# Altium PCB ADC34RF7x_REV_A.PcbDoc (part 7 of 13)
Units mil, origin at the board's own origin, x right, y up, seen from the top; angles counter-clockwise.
Board outline 6250 x 2716.54 mil, 18 copper layers (Top Layer, L2 GND, L3 PWR, L4 GND, L5 PWR/SIG, L6 GND, L7 SIGNAL, L8 GND, L9 GND, L10 SIGNAL, L11 GND, L12 SIGNAL, L13 GND, L14 PWR, L15 GND, L16 PWR/SIG, L16 GND, Bottom Layer), stack 95.314 mil thick; 668 components, 786 nets, 3150 pads, 2020 vias.
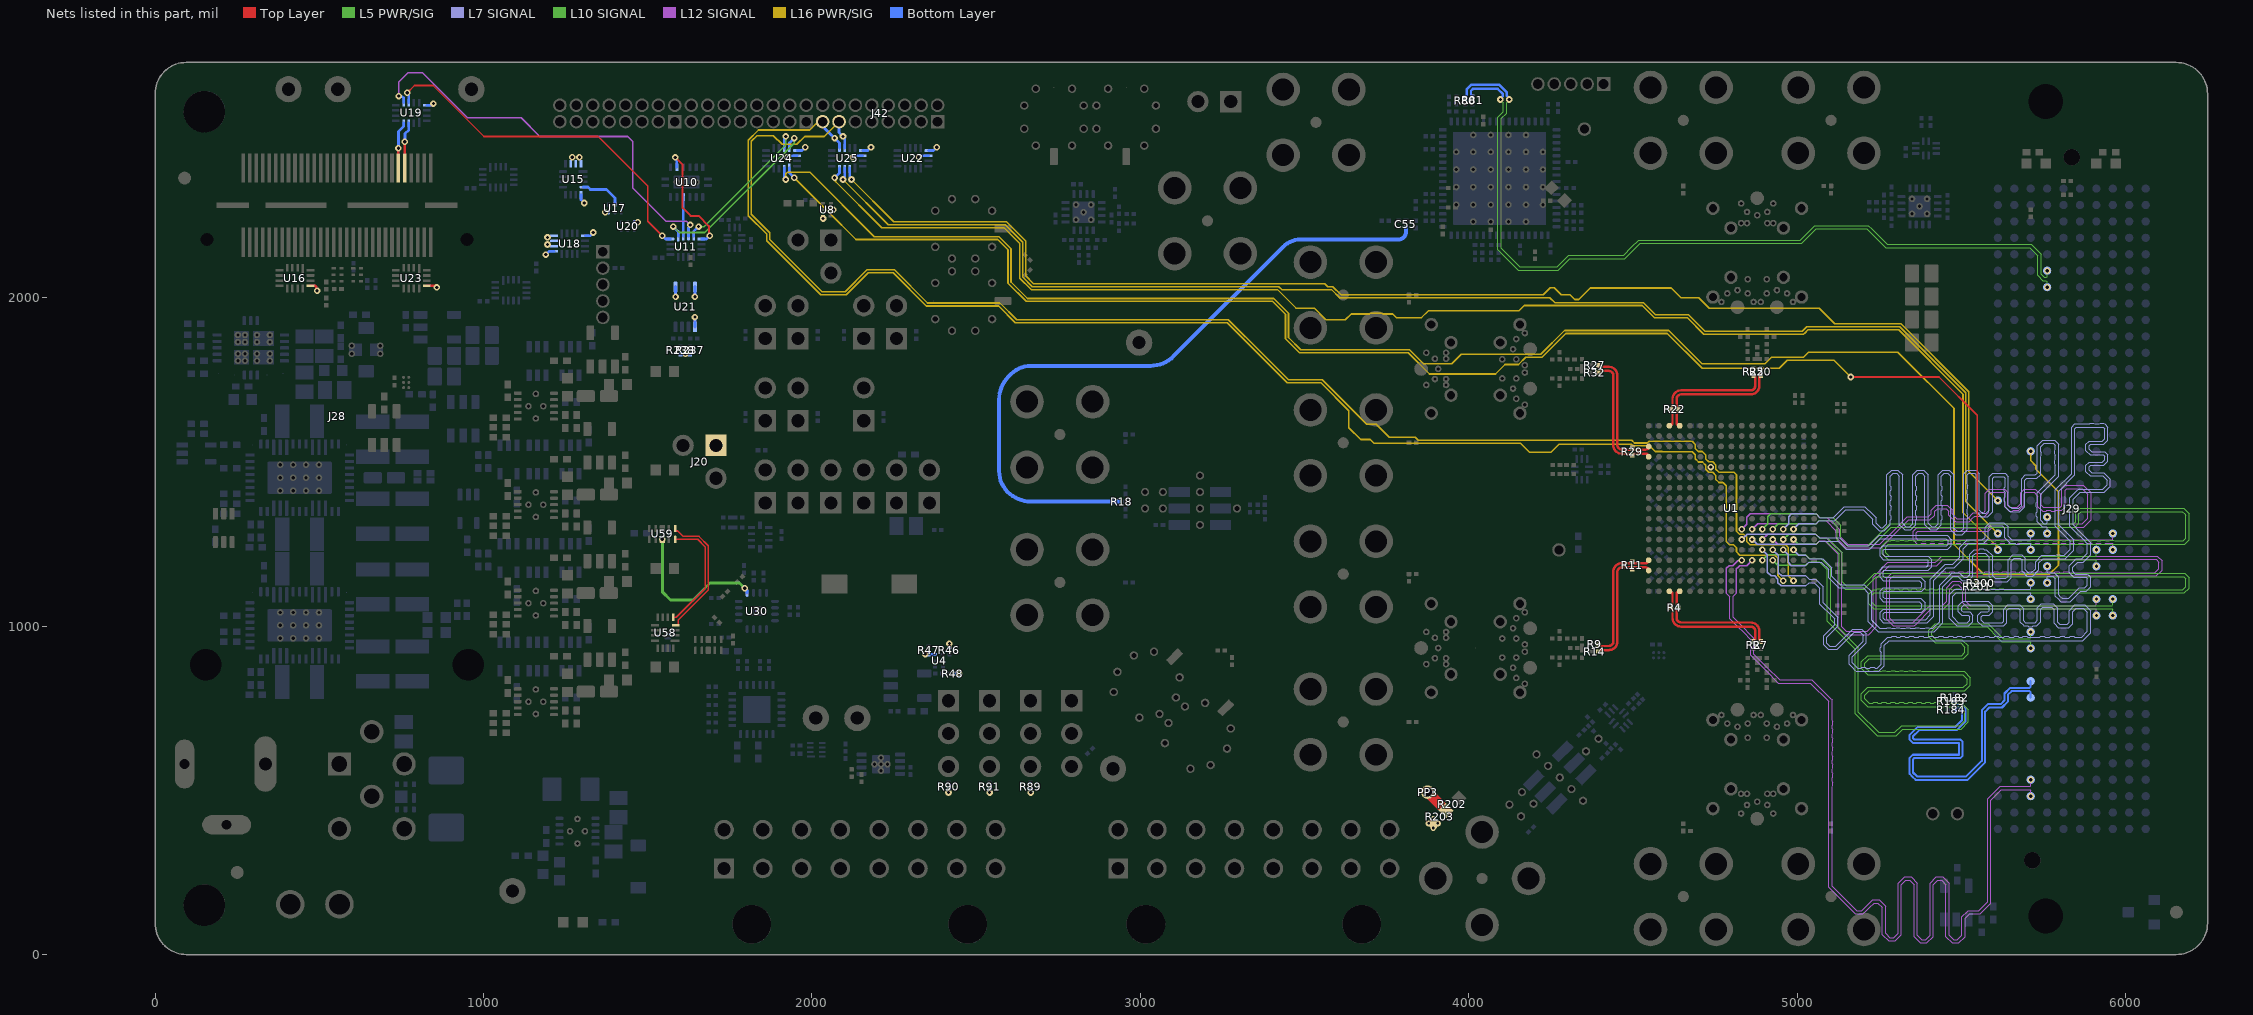
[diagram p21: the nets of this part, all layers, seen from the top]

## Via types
v1: diameter 20, hole 10, Top Layer to Bottom Layer, tented both sides, 1793 vias
v2: diameter 24, hole 12, Top Layer to Bottom Layer, tented both sides, 168 vias
v3: diameter 18, hole 8, Top Layer to Bottom Layer, tented both sides, 59 vias

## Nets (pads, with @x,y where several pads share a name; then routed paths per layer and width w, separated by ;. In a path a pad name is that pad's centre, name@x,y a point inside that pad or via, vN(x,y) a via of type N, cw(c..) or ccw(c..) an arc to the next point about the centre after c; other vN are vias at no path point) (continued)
GPIO21_FPGA: J29.K20 U25.2 | length 4184
  L16 PWR/SIG w5: v1(2120.5,2360.04) 2249.44,2231.1 2592.63,2231.1 2651.15,2172.58 2651.15,2066.73 2675.07,2042.81 3561.6,2042.81 3570.6,2033.81 3586.14,2033.81 3610.95,2009 4226.78,2009 4247.92,2030.15 4260.77,2030.15 4281.92,2009 4308.22,2009 4322.56,1994.66 4335.4,1994.66 4370.4,2029.66 4616.6,2029.66 4646.26,2000 4700.45,2000 4732.45,1968 5067.27,1968 5114.94,1920.33 5316.57,1920.33 5523,1713.9 5523,1470.69 v1(5611.42,1382.27)
  Bottom Layer w8: U25.2@2115.5,2395.04 U25.2@2115.5,2393.07 2115.5,2368.28 2120.5,2363.28 v1(2120.5,2360.04)
GPIO22_ADC: J42.13 U1.C16 U25.10 | length 4520.3
  L16 PWR/SIG w5: J42.13@2082.62,2536.06 2037.62,2491.06 1978.09,2491.06 1954.1,2467.07 1909.24,2467.07 1882.62,2493.69 1832.79,2493.69 1815.27,2476.17 1815.27,2253.78 1871.39,2197.67 1871.39,2177.04 2030.57,2017.86 2101.18,2017.86 2168.05,2084.73 2251.48,2084.73 2352.21,1984 2572.56,1984 2623.36,1933.2 3268.22,1933.2 3374.43,1827 3451.32,1750.11 3553.84,1750.11 3689.65,1614.3 3718.8,1614.3 3758.3,1574.81 3837.19,1574.81 3846.19,1565.81 4496.61,1565.81 4504.64,1557.78 4544.11,1557.78 4549.56,1563.24 4589.03,1563.24 4589.53,1562.74 4680.44,1562.74 4689.84,1553.34 4689.84,1540.99 4699.25,1531.59 4711.59,1531.59 4721.32,1521.86 4721.32,1509.51 4730.71,1500.12 4743.06,1500.12 4752.76,1490.42 4752.76,1478.08 4762.08,1468.75 4807.62,1468.75 4815.5,1460.87 4815.5,1288.9 4825.12,1279.28 4837.92,1279.28 4847,1270.2 4847,1257.4 4856.62,1247.78 4965.21,1247.78 4973.48,1239.52 4973.48,1153.3 v1(4988.98,1137.8)
  Bottom Layer w8: J42.13@2082.62,2536.06 2082.62,2503.19 v1(2094.75,2491.06) 2094.75,2487.81 v1@2099.75,2482.81 ; U25.10@2099.75,2456.06 v1@2099.75,2482.81 ; v1@2099.75,2491.06 v1@2099.75,2482.81
GPIO22_FPGA: J29.K22 U25.3 | length 4266.9
  L16 PWR/SIG w5: v1(2094.75,2360.04) 2232.69,2222.1 2588.91,2222.1 2642.15,2168.85 2642.15,2063 2671.34,2033.81 3421.47,2033.81 3430.47,2024.81 3582.41,2024.81 3607.22,2000 4247.07,2000 4261.84,1985.23 4531.98,1985.23 4569.59,1947.63 4669.8,1947.63 4719.56,1897.87 5015.76,1897.87 5029.22,1911.33 5312.85,1911.33 5514,1710.17 5514,1379.69 v1(5611.42,1282.27)
  Bottom Layer w8: v1(2094.75,2360.04) 2094.75,2363.28 2099.75,2368.28 U25.3@2099.75,2393.07 U25.3@2099.75,2395.04
GPIO23_ADC: J42.15 U1.D16 U25.9 | length 4491.8
  L16 PWR/SIG w5: J42.15@2032.62,2536.06 2025.67,2529.11 2011.4,2529.11 1993.09,2510.8 1837.17,2510.8 1806.27,2479.9 1806.27,2250.06 1862.39,2193.94 1862.39,2173.31 2026.84,2008.86 2104.91,2008.86 2171.78,2075.73 2247.75,2075.73 2348.48,1975 2568.83,1975 2619.63,1924.2 3264.49,1924.2 3368.06,1820.63 3447.59,1741.11 3550.12,1741.11 3635,1656.22 3635,1604.26 3670.84,1568.42 3699.86,1568.42 3711.47,1556.81 4157.97,1556.81 4184.99,1529.79 4250.74,1529.79 4275.29,1554.34 4495.36,1554.34 4500.91,1548.78 4550.68,1548.78 4567.72,1531.74 4589.03,1531.74 4589.53,1531.25 4680.44,1531.25 4690,1521.69 4690,1509.34 4699.56,1499.78 4711.9,1499.78 4721.45,1490.24 4721.45,1477.89 4730.96,1468.38 4743.3,1468.38 4752.76,1458.93 4752.76,1446.58 4762.08,1437.26 4773.63,1437.26 4774.13,1436.76 4774.92,1436.76 4784.01,1427.67 4784.01,1257.85 4794.08,1247.78 4806.42,1247.78 4815.5,1238.7 4815.5,1226.36 4825.59,1216.26 4932.4,1216.26 4941.98,1206.69 4941.98,1153.3 v1(4957.48,1137.8)
  Bottom Layer w8: J42.15@2032.62,2536.06 2039,2529.68 2039,2516.06 2084,2471.06 ; v1(2069,2486.06) 2084,2471.06 ; U25.9@2084,2456.06 2084,2471.06
GPIO23_FPGA: J29.K23 U25.4 | length 4387.9
  L16 PWR/SIG w5: v1(2069,2365.04) 2071.87,2362.17 2071.87,2353.75 2212.52,2213.1 2585.18,2213.1 2633.15,2165.12 2633.15,2059.27 2667.62,2024.81 3417.74,2024.81 3474.1,1968.44 3529.31,1968.44 3564.55,1933.2 3611.21,1933.2 3611.64,1932.77 3624.48,1932.77 3642.05,1950.34 3697.96,1950.34 3699.85,1952.23 3736.27,1952.23 3738.16,1950.34 3768.81,1950.34 3779.6,1939.55 3856.44,1939.55 3877.62,1960.73 4153.42,1960.73 4168.92,1976.23 4528.26,1976.23 4565.86,1938.63 4666.08,1938.63 4715.83,1888.87 5019.49,1888.87 5022.89,1892.27 5032.95,1902.33 5309.12,1902.33 5505,1706.45 5505,1345.93 5608.55,1242.38 5608.55,1235.14 v1(5611.42,1232.27)
  Bottom Layer w8: v1(2069,2365.04) 2084,2380.04 U25.4@2084,2393.07 U25.4@2084,2395.04
GPIO_MUX0_FT: J28.9 U19.3 | length 143.1
  Top Layer w8: J28.9@760.27,2395 v1(760.27,2475)
  Bottom Layer w8: v1(760.27,2475) 761.1,2475.84 761.1,2499.69 772.4,2510.98 U19.3@772.4,2533.03
GPIO_MUX1_FT: J28.11 U19.4 | length 144.6
  Top Layer w8: J28.11@740.91,2395 v1(740.91,2455)
  Bottom Layer w8: v1(740.91,2455) 740.99,2455.08 740.99,2506.07 756.65,2521.73 U19.4@756.65,2533.03
GPIO_MUX_0: U10.13 U11.2 | length 120
  Bottom Layer w8: U11.2@1608.5,2186.65 U10.13@1608.5,2306.65
GPIO_MUX_0_FMC_GPIOVDD: U11.1 U24.12 | length 576.4
  L5 PWR/SIG w5: v1(1577.76,2216.65) 1595.79,2198.62 1674.13,2198.62 1946.25,2470.74 v1(1946.25,2486.06)
  Bottom Layer w8: v1(1577.76,2216.65) 1592.76,2201.65 U11.1@1592.76,2186.65 ; U24.12@1931.25,2456.06 1931.25,2471.06 v1(1946.25,2486.06)
GPIO_MUX_0_FPGA: R200.1 R201.2 U24.1 | length 4674.4
  Top Layer w5: v1(5163.54,1758.63) 5432.03,1758.63 5548.71,1641.96 R200.1@5548.71,1131.13
  L16 PWR/SIG w5: v1(1946.25,2365.04) 2049.54,2261.74 2049.54,2261.63 2134.07,2177.1 2565.75,2177.1 2597.15,2145.7 2597.15,2044.36 2652.7,1988.81 3402.83,1988.81 3442.19,1949.44 3442.19,1875.17 3484.82,1832.55 3815.96,1832.55 3880.74,1767.77 3900.69,1767.77 3913.53,1767.77 4081.5,1767.77 4110.5,1796.77 4151.53,1796.77 4173.53,1818.77 4223.19,1818.77 4295.69,1891.27 4605.06,1891.27 4710.83,1785.5 4945.42,1785.5 4969.79,1809.87 5112.31,1809.87 v1(5163.54,1758.63)
  Bottom Layer w8: U24.1@1931.25,2395.04 1931.25,2380.04 v1(1946.25,2365.04)
GPIO_MUX_0_USB_GPIOVDD: U11.16 U19.10 | length 1099.8
  Top Layer w5: v1(767.4,2624.06) 789.58,2646.23 846.23,2646.23 1001.4,2491.06 1348.94,2491.06 1500,2340 1500,2232.91 v1(1544.13,2188.78)
  Bottom Layer w8: v1(767.4,2624.06) 767.4,2620.81 772.4,2615.81 U19.10@772.4,2594.06 ; v1(1544.13,2188.78) 1544.92,2188.78 1547.22,2186.48 1547.22,2185.69 1554.13,2178.78 U11.16@1569.13,2178.78
GPIO_MUX_1: U10.3 U11.5 | length 357.7
  Top Layer w6: v1(1583.82,2427.2) 1606.24,2404.78 1606.24,2273.71 1630.62,2249.33 1654.83,2249.33 1685.98,2218.18 1685.98,2191.42 v1(1688.62,2188.78)
  Bottom Layer w8: v1(1583.82,2427.2) 1583.82,2423.96 1588.82,2418.96 U10.3@1588.82,2397.2 ; U11.5@1663.62,2178.78 1678.62,2178.78 1685.54,2185.69 1685.54,2186.48 1687.83,2188.78 v1(1688.62,2188.78)
GPIO_MUX_1_FMC_GPIOVDD: U11.4 U24.11 | length 467.6
  L5 PWR/SIG w5: v1(1655,2216.65) 1671.89,2216.65 1920.5,2465.26 v1(1920.5,2491.06)
  Bottom Layer w8: U11.4@1640,2186.65 1640,2201.65 v1(1655,2216.65) ; U24.11@1915.5,2456.06 1915.5,2482.81 1920.5,2487.81 v1(1920.5,2491.06)
GPIO_MUX_1_FPGA: J29.H17 U24.2 | length 5290.3
  L16 PWR/SIG w5: v1(1920.5,2360.04) 1920.5,2377.46 1924.57,2381.54 1994.57,2381.54 2190.02,2186.1 2569.48,2186.1 2606.15,2149.42 2606.15,2048.09 2656.43,1997.81 3406.55,1997.81 3451.19,1953.17 3451.19,1878.9 3488.55,1841.55 3819.69,1841.55 3850.63,1810.61 3862.47,1798.77 3948.04,1798.77 3977.04,1827.77 4219.46,1827.77 4291.96,1900.27 4608.79,1900.27 4709.63,1799.43 4902.87,1799.43 4922.31,1818.87 5019.6,1818.87 5035,1834.27 5306.77,1834.27 5322.17,1818.87 5478,1663.04 5478,1248.27 5568.27,1158 5768.27,1158 5795.92,1185.65 5795.92,1409.35 5726.92,1478.35 5726.92,1488.69 5711.42,1504.19 v1(5711.42,1532.27)
  Bottom Layer w8: U24.2@1915.5,2395.04 U24.2@1915.5,2393.07 1915.5,2368.28 1920.5,2363.28 v1(1920.5,2360.04)
GPIO_MUX_1_USB_GPIOVDD: U11.3 U19.9 | length 1285.5
  L12 SIGNAL w5: v1(741.65,2614.06) 741.65,2656.65 770,2685 814.11,2685 951.43,2547.68 1114.81,2547.68 1171.43,2491.06 1438.94,2491.06 1455,2475 1455,2333.24 1555.65,2232.59 1618.31,2232.59 v1(1629.25,2221.65)
  Bottom Layer w8: v1(741.65,2614.06) 743.95,2611.76 753.1,2611.76 756.65,2608.2 U19.9@756.65,2594.06 ; U11.3@1624.25,2186.65 1624.25,2213.41 1629.25,2218.41 v1(1629.25,2221.65)
GPIOVADJ: PP3.1 R89.2 R90.2 R91.2 R202.2 R203.1 R237.2 R238.2 U15.5 U15.14 U15.15 U15.16 U16.13 U17.6 U18.5 U18.14 U18.15 U18.16 U20.6 U21.1 U21.5 U22.14 U24.14 U25.14 | length 397
  Top Layer w8: U16.13@473.19,2036.26 487.33,2036.26 490.89,2032.7 490.89,2023.56 v1(493.19,2021.26)
  Top Layer w32: PP3.1@3874.91,494.48 R203.1@3931.11,438.29
  Bottom Layer w8: U15.5@1296.98,2313.39 1296.98,2298.39 1303.9,2291.47 1304.68,2291.47 1306.98,2289.17 v1(1306.98,2288.39) ; U18.5@1309.38,2188.62 1324.38,2188.62 1331.3,2195.54 1331.3,2196.32 1333.6,2198.62 v1(1334.38,2198.62) ; R238.2@1599.89,1828.32 v3(1614.89,1828.32) R237.2@1629.18,1828.32 ; v1(1924.87,2427.44) 1928.12,2427.44 1933.12,2432.44 U24.14@1954.87,2432.44 ; v1(2124.87,2427.44) 2128.12,2427.44 2133.12,2432.44 U25.14@2154.87,2432.44 ; v1(2324.87,2427.44) 2328.12,2427.44 2333.12,2432.44 U22.14@2354.87,2432.44 ; v1(2416.05,493.41) R90.2@2416.03,500.5 ; v1(2541.05,493.41) R91.2@2541.03,500.5 ; v1(2666.05,493.41) R89.2@2666.03,500.5
  Bottom Layer w10: v1(1370.63,2260) U17.6@1380.63,2260 ; U20.6@1459.37,2230 v1(1469.37,2230) ; v1(1584.81,2003.16) U21.5@1584.81,2033.16 ; U21.1@1643.87,1911.11 v1(1643.87,1941.11)
  other v1: 1194.89,2162.13 1194.89,2183.62 1270.49,2427.87 1291.98,2427.87
GPIOVDD: J20.1 R46.1 R47.1 R48.1 R203.2 U1.L5 U4.6 U8.2 U8.6 U18.13 U19.13 U21.8 U22.13 U23.13 U24.13 U25.13 | length 268.3
  Top Layer w8: U23.13@827.52,2036.26 852.52,2036.26 cw(c852.52,2031.26) v1(857.52,2031.26) ; v1(2034.12,2241.29) U8.6@2034.13,2248.38 ; U8.2@2057.95,2268.06 v1(2065.04,2268.05)
  Bottom Layer w8: U19.13@827.52,2586.18 842.52,2586.18 ccw(c842.52,2591.18) v1(847.52,2591.18) ; v1(1189.89,2131.38) 1190.68,2131.38 1192.98,2133.68 1192.98,2134.46 1199.89,2141.38 U18.13@1214.89,2141.38 ; U24.13@1954.87,2448.19 1969.87,2448.19 1976.78,2455.1 1976.78,2455.89 1979.08,2458.19 v1(1979.87,2458.19) ; U25.13@2154.87,2448.19 2169.87,2448.19 2176.78,2455.1 2176.78,2455.89 2179.08,2458.19 v1(2179.87,2458.19) ; v1(2345.17,914.8) U4.6@2375.16,914.8 ; U22.13@2354.87,2448.19 2369.87,2448.19 2376.78,2455.1 2376.78,2455.89 2379.08,2458.19 v1(2379.87,2458.19) ; R46.1@2418.79,936.85 v1(2418.79,946.85) ; R48.1@2439.26,855.43 v1(2449.26,855.43)
  Bottom Layer w10: v1(1643.87,2003.16) U21.8@1643.87,2033.16
  other v1: 4737.01,1484.25
  other v3: 3892.13,385.17 3877.99,399.31 3906.28,399.31 3892.13,413.45
I-SENSE-MUX: U30.9 U59.8@1544.55,1264.12 | length 465.7
  L10 SIGNAL w9: v1(1544.55,1264.12) 1544.55,1104.68 1569.43,1079.8 1638.46,1079.8 1689.72,1131.05 1779.29,1131.05 v1(1795.19,1115.15)
  Bottom Layer w9: v1@1794.69,1115.15 v1(1795.19,1115.15) 1802.25,1108.09 U30.9@1802.25,1101.13
I-SENSE-MUX-A0: U58.4 U59.1 | length 412.3
  Top Layer w5: U59.1@1583.92,1296.99 1583.92,1291.17 1585.36,1289.73 1591.18,1289.73 1607.79,1273.12 1656.08,1273.12 1684.39,1244.81 1684.39,1110.11 1593.03,1018.75 1593.03,1004.15 1592.09,1003.21 U58.4@1585.08,1003.21
I-SENSE-MUX-A1: U58.5 U59.10 | length 361.6
  Top Layer w5: U58.5@1577.21,1026.83 1586.97,1026.83 1675.39,1115.25 1675.39,1241.08 1652.35,1264.12 U59.10@1583.92,1264.12
INA_ADC_N: R2.2 R4.2 U1.R17 | length 401.4
  Top Layer w7.4: U1.R17@4611.02,1106.3 cw(c4611.02,1096.75) 4620.57,1096.75 4620.57,1061.12 cw(c4615.75,1061.12) R4.2@4615.75,1056.3 cw(c4615.75,1051.48) 4620.57,1051.48 4620.57,1024.56 ccw(c4646.47,1024.56) 4646.47,998.66 4858.83,998.66 cw(c4858.83,985.16) 4872.33,985.16 4872.33,958.25 cw(c4867.51,958.25) R2.2@4867.51,953.43
INA_ADC_P: R4.1 R7.2 U1.P17 | length 401.4
  Top Layer w7.4: U1.P17@4642.52,1106.3 ccw(c4642.52,1096.75) 4632.97,1096.75 4632.97,1061.12 ccw(c4637.8,1061.12) R4.1@4637.8,1056.3 ccw(c4637.8,1051.48) 4632.97,1051.48 4632.97,1024.56 ccw(c4646.47,1024.56) 4646.47,1011.06 4858.83,1011.06 cw(c4858.83,985.16) 4884.73,985.16 4884.73,958.25 ccw(c4889.56,958.25) R7.2@4889.56,953.43
INB_ADC_N: R9.2 R11.2 U1.U14 | length 401.4
  Top Layer w7.4: R9.2@4395.16,944.3 ccw(c4399.98,944.3) 4399.98,939.48 4426.9,939.48 ccw(c4426.9,952.98) 4440.4,952.98 4440.4,1165.34 cw(c4466.3,1165.34) 4466.3,1191.24 4493.21,1191.24 ccw(c4493.21,1196.06) 4498.03,1196.06 ccw(c4502.86,1196.06) 4502.86,1191.24 4538.48,1191.24 ccw(c4538.48,1200.79) U1.U14@4548.03,1200.79
INB_ADC_P: R11.1 R14.2 U1.U15 | length 401.4
  Top Layer w7.4: R14.2@4395.16,922.25 cw(c4399.98,922.25) 4399.98,927.08 4426.9,927.08 ccw(c4426.9,952.98) 4452.8,952.98 4452.8,1165.34 cw(c4466.3,1165.34) 4466.3,1178.84 4493.21,1178.84 cw(c4493.21,1174.02) R11.1@4498.03,1173.99 cw(c4502.85,1174.02) 4502.85,1178.84 4538.48,1178.84 cw(c4538.48,1169.29) U1.U15@4548.03,1169.29
INC_ADC_N: R20.2 R22.2 U1.P1 | length 401.4
  Top Layer w7.4: U1.P1@4642.52,1610.24 cw(c4642.52,1619.78) 4632.97,1619.78 4632.97,1655.41 cw(c4637.8,1655.41) R22.2@4637.8,1660.24 cw(c4637.8,1665.06) 4632.97,1665.06 4632.97,1691.97 cw(c4646.47,1691.97) 4646.47,1705.47 4858.83,1705.47 ccw(c4858.83,1731.37) 4884.73,1731.37 4884.73,1758.28 cw(c4889.56,1758.28) R20.2@4889.56,1763.11
INC_ADC_P: R22.1 R25.2 U1.R1 | length 401.4
  Top Layer w7.4: U1.R1@4611.02,1610.24 ccw(c4611.02,1619.78) 4620.57,1619.78 4620.57,1655.41 ccw(c4615.75,1655.41) R22.1@4615.75,1660.24 ccw(c4615.75,1665.06) 4620.57,1665.06 4620.57,1691.97 cw(c4646.47,1691.97) 4646.47,1717.87 4858.83,1717.87 ccw(c4858.83,1731.37) 4872.33,1731.37 4872.33,1758.28 ccw(c4867.51,1758.28) R25.2@4867.51,1763.11
IND_ADC_N: R27.2 R29.2 U1.U3 | length 401.4
  Top Layer w7.4: R27.2@4395.16,1794.28 ccw(c4399.98,1794.28) 4399.98,1789.46 4426.9,1789.46 cw(c4426.9,1763.56) 4452.8,1763.56 4452.8,1551.2 ccw(c4466.3,1551.2) 4466.3,1537.7 4493.21,1537.7 ccw(c4493.21,1542.52) R29.2@4498.03,1542.52 ccw(c4502.85,1542.52) 4502.85,1537.7 4538.48,1537.7 ccw(c4538.48,1547.24) U1.U3@4548.03,1547.24
IND_ADC_P: R29.1 R32.2 U1.U4 | length 401.4
  Top Layer w7.4: R32.2@4395.16,1772.23 cw(c4399.98,1772.23) 4399.98,1777.06 4426.9,1777.06 cw(c4426.9,1763.56) 4440.4,1763.56 4440.4,1551.2 ccw(c4466.3,1551.2) 4466.3,1525.3 4493.21,1525.3 cw(c4493.21,1520.47) R29.1@4498.03,1520.47 cw(c4502.86,1520.47) 4502.86,1525.3 4538.48,1525.3 cw(c4538.48,1515.75) U1.U4@4548.03,1515.75
LMK_CLK: C55.1 R18.1 | length 2107.2
  Bottom Layer w12.1: R18.1@2932.95,1379.43 2667,1379.43 cw(c2667,1479.43) 2596.29,1408.71 2596.16,1408.84 cw(c2659.33,1472) 2570,1472 2570,1689.58 cw(c2670,1689.58) 2599.29,1760.29 2606.67,1767.67 cw(c2667,1707.35) 2667,1792.66 3031.06,1792.66 ccw(c3031.06,1892.66) 3101.77,1821.95 3434.82,2155 cw(c3488.43,2101.38) 3488.43,2177.21 3786.13,2177.21 ccw(c3786.13,2199.99) 3808.91,2199.99 C55.1@3808.91,2212.16
LMK_CORECLK_N: J29.G7 R81.2 | length 2482.5
  L10 SIGNAL w3.5: v1(4096.71,2603.54) 4096.71,2601.88 4105.21,2593.38 4105.21,2566.19 4089.08,2550.06 4089.08,2146.29 4151.14,2084.23 4273.23,2084.23 4308.29,2119.3 4475.79,2119.3 4506.93,2150.43 4522.16,2165.66 5014.33,2165.66 5058.18,2209.51 5212.57,2209.51 5219.64,2202.44 5269.81,2152.27 5708.55,2152.27 5713.8,2147.02 5720.87,2139.95 5732.75,2128.07 5732.75,2067.87 5748.36,2052.27 5759.37,2052.27 5761.42,2050.22 v1(5761.42,2032.27)
  Bottom Layer w7.4: R81.2@4012.09,2611.93 4012.09,2612.72 4006.96,2617.85 4006.96,2630.12 4012.68,2635.84 4088.48,2635.84 4104.01,2620.31 4104.01,2614.18 4096.71,2606.88 v1(4096.71,2603.54)
LMK_CORECLK_P: J29.G6 R80.2 | length 2507.1
  L10 SIGNAL w3.5: v1(4123.71,2603.54) 4123.71,2601.88 4115.21,2593.38 4115.21,2562.05 4099.08,2545.92 4099.08,2150.43 4155.28,2094.23 4269.09,2094.23 4304.15,2129.3 4471.65,2129.3 4496.93,2154.57 4518.01,2175.66 4585.21,2175.66 5010.19,2175.66 5054.04,2219.51 5216.71,2219.51 5226.71,2209.51 5273.95,2162.27 5712.69,2162.27 5727.94,2147.02 5742.75,2132.21 5742.75,2072.02 5752.5,2062.27 5759.37,2062.27 5761.42,2064.32 v1(5761.42,2082.27)
  Bottom Layer w7.4: R80.2@3989.44,2611.93 3989.44,2612.72 3994.56,2617.85 3994.56,2635.26 4007.55,2648.24 4093.62,2648.24 4116.41,2625.45 4116.41,2614.18 4123.71,2606.88 v1(4123.71,2603.54)
LMK_SDO_VADJ: U15.4 U17.2 | length 131.2
  Bottom Layer w8: U15.4@1302.89,2337.01 U15.4@1304.86,2337.01 1317.89,2337.01 1325.39,2329.51 1374.63,2329.51 1400.32,2303.82 U17.2@1400.31,2283.82
LVDS12A_N: J29.H31 R182.1 R183.1 | length 1255.2
  Bottom Layer w6.25: R182.1@5480.09,770.74 5483.04,767.79 5483.04,767.73 5487.73,763.04 5500.71,763.04 5513.04,750.7 5513.04,709.96 5488.73,685.64 5486.21,683.13 5371.54,683.13 5353.08,664.67 5353.08,658.47 5356.74,654.81 5497.08,654.81 5503.08,648.8 5503.08,604.06 5497.08,598.06 5356.74,598.06 5353.08,594.4 5353.08,554.16 5365,542.24 5506.21,542.24 5515.01,542.24 5562.52,589.75 5562.52,743.94 5581.12,762.54 5619.59,762.54 5631.44,774.4 5631.44,794.68 5649,812.24 5707.88,812.24 5711.42,815.78 J29.H31@5711.42,832.27
LVDS12A_P: J29.H32 R184.1 | length 1254.8
  Bottom Layer w6.25: R184.1@5480.09,745.74 5483.04,748.69 5483.04,748.75 5487.08,752.79 5496.46,752.79 5502.79,746.46 5502.79,714.2 5481.97,693.38 5367.29,693.38 5359.56,685.64 5342.83,668.92 5342.83,654.22 5352.5,644.56 5492.83,644.56 5492.83,608.31 5352.5,608.31 5342.83,598.64 5342.83,549.91 5350.97,541.77 5360.75,531.99 5519.25,531.99 5572.77,585.5 5572.77,739.69 5585.37,752.29 5623.83,752.29 5641.69,770.16 5641.69,790.44 5653.25,801.99 5708.18,801.99 5711.42,798.75 J29.H32@5711.42,782.27
LVDSA0_N: J29.C23 U1.G11 | length 2757
  L12 SIGNAL w3.5: 5058.18,1311.77 5068.18,1321.77 5086.83,1321.77 5119.35,1289.25 5119.35,1269.65 5150.22,1238.78 5255.71,1238.78 5302.35,1285.42 5340.17,1323.24 5404.21,1323.24 5419.19,1338.22 5419.19,1349.4 5427.84,1358.04 5453.76,1358.04 5457.9,1353.9 5461.97,1349.84 5461.97,1338.2 5482.54,1317.63 5523.61,1317.63 5526.54,1320.56 5534.1,1328.13 5541.22,1335.25 5555.99,1335.25 5558.57,1332.67 5569.31,1332.67 5583.22,1346.58 5583.22,1401.09 5589.65,1407.52 5628.39,1407.52 5631.71,1404.2 5631.71,1363.54 5645.57,1349.69 5656.3,1349.69 5658.88,1352.27 5675.14,1352.27 5691.62,1368.74 5691.62,1402.64 5696.5,1407.52 5721.76,1407.52 5732.05,1397.24 5733.58,1395.7 5733.58,1363.54 5744.86,1352.27 5747.44,1349.69 5758.18,1349.69 5760.76,1352.27 5771.49,1352.27 5774.07,1349.69 5784.81,1349.69 5787.39,1352.27 5805.93,1352.27 5815.93,1362.27 5815.93,1413.93 5820.71,1418.71 5867.63,1418.71 5885,1401.34 5885,1328.64 5868.13,1311.77 5590.45,1311.77 5584.59,1305.91 5578.09,1299.42 5364,1299.42 5353.57,1289 5353.57,1262.67 5366.55,1249.69 5377.29,1249.69 5379.87,1252.27 5390.61,1252.27 5393.19,1249.69 5403.93,1249.69 5406.51,1252.27 5417.24,1252.27 5419.82,1249.69 5430.56,1249.69 5433.14,1252.27 5443.88,1252.27 5446.46,1249.69 5457.2,1249.69 5459.78,1252.27 5470.52,1252.27 5473.1,1249.69 5483.83,1249.69 5486.41,1252.27 5497.15,1252.27 5499.73,1249.69 5510.47,1249.69 5513.05,1252.27 5523.79,1252.27 5526.37,1249.69 5537.1,1249.69 5539.68,1252.27 5550.42,1252.27 5553,1249.69 5563.74,1249.69 5566.32,1252.27 5577.06,1252.27 5579.64,1249.69 5590.38,1249.69 5592.96,1252.27 5603.69,1252.27 5606.27,1249.69 5617.01,1249.69 5619.59,1252.27 5630.33,1252.27 5632.91,1249.69 5643.65,1249.69 5646.23,1252.27 5656.96,1252.27 5659.54,1249.69 5670.28,1249.69 5672.86,1252.27 5683.6,1252.27 5686.18,1249.69 5696.92,1249.69 5699.5,1252.27 5710.24,1252.27 5712.82,1249.69 5723.55,1249.69 5726.13,1252.27 5736.87,1252.27 5739.45,1249.69 5750.19,1249.69 5752.77,1252.27 5763.51,1252.27 5766.09,1249.69 5776.82,1249.69 5779.4,1252.27 5790.14,1252.27 5792.72,1249.69 5803.46,1249.69 5806.04,1252.27 5816.78,1252.27 5819.36,1249.69 5830.1,1249.69 5832.68,1252.27 5843.41,1252.27 5845.99,1249.69 5856.73,1249.69 5859.31,1252.27 5870.05,1252.27 5872.63,1249.69 5883.37,1249.69 5885.95,1252.27 5896.69,1252.27 5899.26,1249.69 5910,1249.69 5912.58,1252.27 5923.32,1252.27 5925.9,1249.69 5936.64,1249.69 5939.22,1252.27 5959.37,1252.27 5961.42,1250.22 v1(5961.42,1232.27)
  L12 SIGNAL w4: v1(4862.99,1295.28) 4879.49,1311.77 5058.18,1311.77
LVDSA0_P: J29.C22 U1.H11 | length 2757.8
  L12 SIGNAL w3.5: 5058.18,1341.77 5068.18,1331.77 5090.97,1331.77 5129.35,1293.39 5129.35,1273.79 5154.36,1248.78 5251.57,1248.78 5292.35,1289.56 5336.03,1333.24 5400.07,1333.24 5409.19,1342.36 5409.19,1353.54 5423.69,1368.04 5457.9,1368.04 5460.83,1365.11 5471.97,1353.98 5471.97,1342.35 5486.69,1327.63 5519.47,1327.63 5537.08,1345.25 5567.75,1345.25 5573.22,1350.72 5573.22,1405.23 5585.51,1417.52 5632.54,1417.52 5641.71,1408.34 5641.71,1367.68 5647.13,1362.27 5671,1362.27 5681.62,1372.89 5681.62,1406.78 5692.35,1417.52 5725.91,1417.52 5739.12,1404.31 5743.58,1399.84 5743.58,1367.68 5749,1362.27 5801.79,1362.27 5805.93,1366.41 5805.93,1418.07 5816.57,1428.71 5871.78,1428.71 5874.71,1425.78 5895,1405.48 5895,1324.5 5872.27,1301.77 5594.59,1301.77 5582.23,1289.42 5368.14,1289.42 5363.57,1284.85 5363.57,1266.81 5368.12,1262.27 5959.37,1262.27 5961.42,1264.32 v1(5961.42,1282.27)
  L12 SIGNAL w4: v1(4831.5,1295.28) 4846.75,1310.53 4846.75,1331.74 4856.78,1341.77 5058.18,1341.77
LVDSA1_N: J29.D24 U1.E11 | length 3161.2
  L10 SIGNAL w3.5: 5058.18,1311.77 5068.18,1321.77 5103.77,1321.77 5122.7,1302.84 5122.7,1261.46 5149.36,1234.8 5219.13,1234.8 5286.1,1301.77 5846.79,1301.77 5858.4,1313.37 5858.4,1341.5 5865.9,1349 6173.13,1349 6180.63,1341.5 6184,1338.13 6184,1267.04 6176.49,1259.53 5966.58,1259.53 5964,1262.11 5953.26,1262.11 5950.68,1259.53 5939.94,1259.53 5937.36,1262.11 5926.62,1262.11 5924.04,1259.53 5913.31,1259.53 5910.73,1262.11 5899.99,1262.11 5897.41,1259.53 5886.67,1259.53 5884.09,1262.11 5873.35,1262.11 5870.77,1259.53 5860.04,1259.53 5857.46,1262.11 5846.72,1262.11 5844.14,1259.53 5833.4,1259.53 5830.82,1262.11 5820.08,1262.11 5817.5,1259.53 5806.76,1259.53 5804.18,1262.11 5793.45,1262.11 5790.87,1259.53 5780.13,1259.53 5777.55,1262.11 5766.81,1262.11 5764.23,1259.53 5753.49,1259.53 5750.91,1262.11 5740.18,1262.11 5737.6,1259.53 5726.86,1259.53 5724.28,1262.11 5713.54,1262.11 5710.96,1259.53 5700.22,1259.53 5697.64,1262.11 5686.9,1262.11 5684.32,1259.53 5673.59,1259.53 5671.01,1262.11 5660.27,1262.11 5657.69,1259.53 5646.95,1259.53 5644.37,1262.11 5633.63,1262.11 5631.05,1259.53 5620.31,1259.53 5617.74,1262.11 5607,1262.11 5604.42,1259.53 5593.68,1259.53 5591.1,1262.11 5580.36,1262.11 5577.78,1259.53 5567.04,1259.53 5564.46,1262.11 5553.73,1262.11 5551.15,1259.53 5540.41,1259.53 5537.83,1262.11 5527.09,1262.11 5524.51,1259.53 5513.77,1259.53 5511.19,1262.11 5500.45,1262.11 5497.87,1259.53 5487.14,1259.53 5484.56,1262.11 5473.82,1262.11 5471.24,1259.53 5460.5,1259.53 5457.92,1262.11 5447.18,1262.11 5444.6,1259.53 5433.87,1259.53 5431.29,1262.11 5420.55,1262.11 5417.97,1259.53 5407.23,1259.53 5404.65,1262.11 5393.91,1262.11 5391.33,1259.53 5380.59,1259.53 5378.01,1262.11 5367.28,1262.11 5364.7,1259.53 5353.96,1259.53 5351.38,1262.11 5340.64,1262.11 5338.06,1259.53 5327.32,1259.53 5324.74,1262.11 5314.01,1262.11 5311.43,1259.53 5300.69,1259.53 5298.11,1262.11 5287.37,1262.11 5284.79,1259.53 5274.05,1259.53 5259.32,1244.8 5259.32,1219.82 5276.87,1202.27 5909.37,1202.27 5911.42,1200.22 v1(5911.42,1182.27)
  L10 SIGNAL w4: v1(4925.98,1295.28) 4942.48,1311.77 5058.18,1311.77
LVDSA1_P: J29.D23 U1.F11 | length 3162
  L10 SIGNAL w3.5: 5058.18,1341.77 5068.18,1331.77 5107.92,1331.77 5132.7,1306.99 5132.7,1265.6 5153.5,1244.8 5214.99,1244.8 5281.96,1311.77 5842.65,1311.77 5848.4,1317.52 5848.4,1345.64 5861.76,1359 6177.27,1359 6187.7,1348.57 6194,1342.27 6194,1298.08 6194,1262.9 6180.63,1249.53 5278.19,1249.53 5269.32,1240.66 5269.32,1223.96 5281.02,1212.27 5909.37,1212.27 5911.42,1214.32 v1(5911.42,1232.27)
  L10 SIGNAL w4: v1(4894.49,1295.28) 4910.98,1311.77 4910.98,1332.98 4919.77,1341.77 5058.18,1341.77
LVDSA2_N: J29.G22 U1.C11 | length 2866.1
  L7 SIGNAL w3.5: 5051.12,1311.77 5057.83,1311.77 5066.73,1320.67 5114.7,1320.67 5148.26,1354.23 5202.16,1354.23 5222.87,1333.52 5231.03,1325.36 5231.03,1309.7 5250.77,1289.96 5265.36,1289.96 5283.51,1308.11 5283.51,1322.17 5286.08,1324.75 5286.08,1335.48 5283.51,1338.06 5283.51,1352.12 5286.08,1354.7 5286.08,1365.44 5283.51,1368.02 5283.51,1382.08 5286.08,1384.66 5286.08,1395.4 5283.51,1397.98 5283.51,1412.04 5286.08,1414.62 5286.08,1425.36 5283.51,1427.94 5283.51,1456.34 5292.1,1464.93 5303.09,1464.93 5311.42,1456.6 5311.42,1309.19 5327.34,1293.27 5346.66,1293.27 5361.5,1308.11 5361.5,1322.17 5364.08,1324.75 5364.08,1335.49 5361.5,1338.06 5361.5,1352.12 5364.08,1354.7 5364.08,1365.44 5361.5,1368.02 5361.5,1382.08 5364.08,1384.66 5364.08,1395.4 5361.5,1397.98 5361.5,1412.04 5364.08,1414.62 5364.08,1425.36 5361.5,1427.94 5361.5,1456.34 5370.1,1464.93 5381.09,1464.93 5389.42,1456.6 5389.42,1309.19 5405.34,1293.27 5424.66,1293.27 5439.5,1308.11 5439.5,1322.17 5442.08,1324.75 5442.08,1335.49 5439.5,1338.07 5439.5,1352.12 5442.08,1354.7 5442.08,1365.44 5439.5,1368.02 5439.5,1382.08 5442.08,1384.66 5442.08,1395.4 5439.5,1397.98 5439.5,1412.04 5442.08,1414.62 5442.08,1425.36 5439.5,1427.94 5439.5,1456.34 5448.1,1464.93 5459.09,1464.93 5467.42,1456.6 5467.42,1294.19 5483.34,1278.27 5502.66,1278.27 5517.5,1293.11 5517.5,1326.07 5520.08,1328.65 5520.08,1339.39 5517.5,1341.97 5517.5,1356.03 5520.08,1358.61 5520.08,1369.35 5517.5,1371.93 5517.5,1385.99 5520.08,1388.57 5520.08,1399.31 5517.5,1401.89 5517.5,1415.95 5520.08,1418.53 5520.08,1429.26 5517.5,1431.84 5517.5,1460.24 5522.19,1464.93 5540.71,1464.93 5545.42,1460.23 5545.42,1349.19 5561.34,1333.27 5580.66,1333.27 5595.5,1348.11 5595.5,1450.18 5600.25,1454.93 5629.32,1454.93 5633.41,1450.84 5633.41,1424.1 5630.83,1421.52 5630.83,1410.79 5633.41,1408.21 5633.41,1394.15 5630.83,1391.57 5630.83,1380.83 5633.41,1378.25 5633.41,1364.19 5649.34,1348.27 5678.66,1348.27 5693.5,1363.11 5693.5,1444.26 5699.43,1450.2 5730.01,1450.2 5741.41,1461.6 5741.41,1515.76 5743.99,1518.34 5743.99,1529.08 5741.41,1531.66 5741.41,1545.72 5752.38,1556.69 5780.37,1556.69 5786.67,1550.39 5786.67,1536.33 5784.09,1533.75 5784.09,1523.01 5786.67,1520.43 5786.67,1506.37 5784.09,1503.79 5784.09,1493.05 5786.67,1490.47 5786.67,1461.17 5781.28,1455.79 5731.41,1405.92 5731.41,1377.54 5728.83,1374.96 5728.83,1364.23 5731.41,1361.65 5731.41,1347.59 5728.83,1345.01 5728.83,1334.27 5731.41,1331.69 5731.41,1317.63 5734.34,1314.7 5746.77,1302.27 5759.37,1302.27 5761.42,1300.22 v1(5761.42,1282.27)
  L7 SIGNAL w4: v1(4988.98,1295.28) 5005.47,1311.77 5051.12,1311.77
LVDSA2_P: J29.G21 U1.D11 | length 2874.2
  L7 SIGNAL w3.5: 5051.12,1341.77 5057.83,1341.77 5068.93,1330.67 5110.56,1330.67 5144.12,1364.23 5206.3,1364.23 5229.94,1340.59 5241.03,1329.5 5241.03,1313.84 5254.91,1299.96 5261.22,1299.96 5273.51,1312.25 5273.51,1460.48 5287.96,1474.93 5307.24,1474.93 5321.42,1460.74 5321.42,1313.33 5331.48,1303.27 5342.52,1303.27 5351.5,1312.25 5351.5,1460.48 5365.95,1474.93 5385.23,1474.93 5399.42,1460.74 5399.42,1313.33 5409.48,1303.27 5420.52,1303.27 5429.5,1312.25 5429.5,1460.48 5443.95,1474.93 5463.23,1474.93 5477.42,1460.75 5477.42,1298.33 5487.48,1288.27 5498.52,1288.27 5507.5,1297.25 5507.5,1464.38 5518.05,1474.93 5544.86,1474.93 5555.42,1464.37 5555.42,1353.33 5565.48,1343.27 5576.52,1343.27 5585.5,1352.25 5585.5,1454.32 5596.11,1464.93 5633.46,1464.93 5643.41,1454.98 5643.41,1368.33 5653.48,1358.27 5674.52,1358.27 5683.5,1367.25 5683.5,1448.41 5695.29,1460.2 5725.87,1460.2 5731.41,1465.74 5731.41,1549.86 5748.24,1566.69 5784.51,1566.69 5796.67,1554.53 5796.67,1457.03 5785.42,1445.79 5741.41,1401.78 5741.41,1321.77 5750.92,1312.27 5759.37,1312.27 5761.42,1314.32 v1(5761.42,1332.27)
  L7 SIGNAL w4: v1(4957.48,1295.28) 4973.98,1311.77 4973.98,1332.98 4982.76,1341.77 5051.12,1341.77
LVDSA3_N: J29.H23 U1.G12 | length 2563.7
  L7 SIGNAL w3.5: 5055.26,1248.78 5057.83,1248.78 5067.4,1258.35 5125.76,1258.35 5149.5,1234.6 5221.72,1234.6 5253.58,1266.46 5452.56,1266.46 5459.57,1259.45 5459.57,1248.75 5455.23,1244.41 5261.45,1244.41 5252.75,1235.71 5252.75,1212.55 5262.95,1202.35 5395.61,1202.35 5399.57,1198.39 5399.57,1184.63 5395.23,1180.29 5261.45,1180.29 5252.75,1171.59 5252.75,1148.43 5262.95,1138.23 5372.56,1138.23 5379.57,1131.22 5379.57,1120.52 5375.23,1116.17 5261.85,1116.17 5252.75,1107.08 5252.75,1084.32 5262.95,1074.12 5372.56,1074.12 5379.57,1067.11 5379.57,1056.4 5375.23,1052.06 5263.06,1052.06 5252.75,1041.75 5252.75,1020.2 5262.95,1010 5396.02,1010 5415.97,1029.95 5415.97,1139.21 5454.95,1178.19 5478.7,1178.19 5505.56,1205.04 5505.56,1235.55 5522.27,1252.27 5568.19,1252.27 5582.25,1266.33 5582.25,1297.03 5590.19,1304.97 5625.28,1304.97 5632.3,1297.96 5632.3,1269.73 5649.76,1252.27 5663.82,1252.27 5666.4,1249.69 5677.14,1249.69 5679.72,1252.27 5709.37,1252.27 5711.42,1250.22 v1(5711.42,1232.27)
  L7 SIGNAL w4: v1(4862.99,1263.78) 4877.99,1248.78 5055.26,1248.78
LVDSA3_P: J29.H22 U1.H12 | length 2594.3
  L7 SIGNAL w3.5: 5055.26,1279.28 5057.33,1279.28 5068.26,1268.35 5129.9,1268.35 5153.65,1244.6 5217.58,1244.6 5249.44,1276.46 5456.71,1276.46 5469.58,1263.59 5469.58,1259.46 ; 5262.66,1231.48 5265.59,1234.41 5459.37,1234.41 5469.57,1244.6 5469.57,1259.45 ; 5262.75,1231.48 5262.75,1216.69 5267.09,1212.35 5399.76,1212.35 5409.57,1202.53 5409.57,1180.49 5399.37,1170.29 5265.59,1170.29 5262.75,1167.45 5262.75,1152.57 5267.09,1148.23 5376.71,1148.23 5389.58,1135.36 5389.58,1131.23 ; 5389.57,1067.11 5389.57,1052.26 5379.37,1042.06 5267.2,1042.06 5262.75,1037.61 5262.75,1024.34 5267.09,1020 5391.88,1020 5405.97,1034.09 5405.97,1143.35 5450.81,1188.19 5474.56,1188.19 5495.56,1209.18 5495.56,1239.7 5518.13,1262.27 5564.05,1262.27 5572.25,1270.47 5572.25,1301.17 5586.05,1314.97 5629.43,1314.97 5642.3,1302.1 5642.3,1273.87 5653.9,1262.27 5709.37,1262.27 5711.42,1264.32 v1(5711.42,1282.27) ; 5389.57,1131.22 5389.57,1116.37 5379.37,1106.17 5265.99,1106.17 5262.75,1102.93 5262.75,1088.46 5267.09,1084.12 5376.71,1084.12 5389.58,1071.24 5389.58,1067.12
  L7 SIGNAL w4: v1(4831.5,1263.78) 4847.5,1279.78 4887.36,1279.78 4887.86,1279.28 5055.26,1279.28
LVDSA4_N: J29.D27 U1.E12 | length 3436.2
  L12 SIGNAL w3.5: 5058.18,1248.78 5068.68,1259.28 5084.85,1259.28 5125.56,1218.58 5125.56,993.34 5145.08,973.81 5217.46,973.81 5241.57,997.92 5241.57,1145.42 5250.68,1154.54 5280.44,1184.29 5425.3,1184.29 5437.63,1196.62 5444.01,1203 6093.14,1203 6101.69,1194.46 6101.69,1174.86 6089.82,1163 5826.07,1163 5823.49,1165.58 5812.75,1165.58 5810.17,1163 5799.43,1163 5796.85,1165.58 5786.11,1165.58 5783.53,1163 5772.8,1163 5770.22,1165.58 5759.48,1165.58 5756.9,1163 5746.16,1163 5743.58,1165.58 5732.84,1165.58 5730.26,1163 5719.52,1163 5716.94,1165.58 5706.21,1165.58 5703.63,1163 5692.89,1163 5690.31,1165.58 5679.57,1165.58 5676.99,1163 5666.25,1163 5663.67,1165.58 5652.94,1165.58 5650.36,1163 5639.62,1163 5637.04,1165.58 5626.3,1165.58 5623.72,1163 5612.98,1163 5610.4,1165.58 5599.66,1165.58 5597.08,1163 5586.35,1163 5583.77,1165.58 5573.03,1165.58 5570.45,1163 5559.71,1163 5557.13,1165.58 5546.39,1165.58 5543.81,1163 5533.08,1163 5530.5,1165.58 5519.76,1165.58 5517.18,1163 5506.44,1163 5503.86,1165.58 5493.12,1165.58 5490.54,1163 5479.8,1163 5477.22,1165.58 5466.49,1165.58 5463.91,1163 5453.17,1163 5450.59,1165.58 5439.85,1165.58 5437.27,1163 5289.45,1163 5272.58,1146.13 5272.58,1020.17 5292.2,1000.56 5356.55,1000.56 5362.41,1006.41 5408.27,1052.27 5437.27,1052.27 5446.09,1052.27 5465.43,1071.6 5465.43,1112.53 5478.9,1126 5490.45,1126 5503.93,1112.53 5503.93,1071.6 5523.26,1052.27 5635.9,1052.27 5909.37,1052.27 5911.42,1050.22 v1(5911.42,1032.27)
  L12 SIGNAL w4: v1(4925.98,1263.78) 4940.98,1248.78 5058.18,1248.78
LVDSA4_P: J29.D26 U1.F12 | length 3436
  L12 SIGNAL w3.5: 5057.18,1279.78 5067.68,1269.28 5089,1269.28 5102.51,1255.76 5135.56,1222.72 5135.56,997.48 5149.22,983.81 5213.32,983.81 5231.57,1002.06 5231.57,1149.57 5246.54,1164.54 5276.29,1194.29 5421.16,1194.29 5427.63,1200.76 5439.87,1213 6097.28,1213 6111.69,1198.6 6111.69,1170.72 6093.97,1153 5293.59,1153 5282.58,1141.99 5282.58,1024.32 5296.34,1010.56 5352.41,1010.56 5404.12,1062.27 5437.27,1062.27 5441.95,1062.27 5455.43,1075.74 5455.43,1116.67 5474.76,1136 5494.59,1136 5513.93,1116.67 5513.93,1075.74 5527.4,1062.27 5635.9,1062.27 5909.37,1062.27 5911.42,1064.32 v1(5911.42,1082.27)
  L12 SIGNAL w4: v1(4894.49,1263.78) 4910.49,1279.78 5057.18,1279.78
LVDSA5_N: J29.C27 U1.C12 | length 3165.1
  L10 SIGNAL w3.5: 5058.18,1248.78 5067.47,1258.06 5089.45,1258.06 5127.69,1219.82 5127.69,1130.95 5145.96,1112.68 5203.22,1112.68 5241.11,1150.57 6177.02,1150.57 6184,1143.59 6184,1119.98 6175.02,1111 5630.8,1111 5628.22,1113.58 5617.49,1113.58 5614.91,1111 5604.17,1111 5601.59,1113.58 5590.85,1113.58 5588.27,1111 5577.53,1111 5574.95,1113.58 5564.21,1113.58 5561.64,1111 5550.9,1111 5548.32,1113.58 5537.58,1113.58 5535,1111 5524.26,1111 5521.68,1113.58 5510.94,1113.58 5508.36,1111 5497.63,1111 5495.05,1113.58 5484.31,1113.58 5481.73,1111 5470.99,1111 5468.41,1113.58 5457.67,1113.58 5455.09,1111 5444.35,1111 5441.77,1113.58 5431.04,1113.58 5428.46,1111 5417.72,1111 5415.14,1113.58 5404.4,1113.58 5401.82,1111 5391.08,1111 5388.5,1113.58 5377.77,1113.58 5375.19,1111 5364.45,1111 5361.87,1113.58 5351.13,1113.58 5348.55,1111 5337.81,1111 5335.23,1113.58 5324.49,1113.58 5321.91,1111 5311.18,1111 5308.6,1113.58 5297.86,1113.58 5295.28,1111 5284.54,1111 5281.96,1113.58 5271.22,1113.58 5268.64,1111 5257.91,1111 5255.33,1113.58 5244.59,1113.58 5242.01,1111 5231.27,1111 5217.95,1097.68 5217.95,1068.49 5234.17,1052.27 5266.89,1052.27 5959.37,1052.27 5961.42,1050.22 v1(5961.42,1032.27)
  L10 SIGNAL w4: v1(4988.98,1263.78) 5003.98,1248.78 5058.18,1248.78
LVDSA5_P: J29.C26 U1.D12 | length 3166.3
  L10 SIGNAL w3.5: 5056.69,1280.28 5068.9,1268.06 5093.59,1268.06 5137.69,1223.96 5137.69,1135.09 5150.1,1122.68 5199.08,1122.68 5236.97,1160.57 6181.16,1160.57 6194,1147.73 6194,1115.84 6179.16,1101 5235.41,1101 5227.95,1093.54 5227.95,1072.63 5238.32,1062.27 5257.74,1062.27 5262.74,1062.27 5959.37,1062.27 5961.42,1064.32 v1(5961.42,1082.27)
  L10 SIGNAL w4: v1(4957.48,1263.78) 4973.98,1280.28 5056.69,1280.28
LVDSA6_N: J29.H25 U1.E13 | length 2839.9
  L7 SIGNAL w3.5: 5026.69,1152.8 5036.69,1142.8 5056.11,1142.8 5079.72,1119.19 5079.72,1071.27 5123.97,1027.02 5123.97,999.68 5090.82,966.52 5090.82,947.46 5098.98,939.3 5118.04,939.3 5169.68,990.94 5197.02,990.94 5211.05,976.92 5211.05,949.57 5168.33,906.86 5168.33,887.8 5182.94,873.19 5184.13,872 5194.87,872 5197.45,874.58 5208.18,874.58 5210.76,872 5221.5,872 5224.08,874.58 5234.82,874.58 5237.4,872 5244.71,872 5256,883.29 5256,921.18 5253.42,923.76 5253.42,934.5 5256,937.08 5256,945.82 5276.18,966 5286.92,966 5289.5,968.58 5300.24,968.58 5302.82,966 5313.55,966 5316.13,968.58 5326.87,968.58 5329.45,966 5340.19,966 5342.77,968.58 5353.51,968.58 5356.09,966 5370.15,966 5372.73,968.58 5383.47,968.58 5386.05,966 5400.11,966 5402.69,968.58 5413.42,968.58 5416,966 5430.06,966 5432.64,968.58 5443.38,968.58 5445.96,966 5460.02,966 5462.6,968.58 5473.34,968.58 5475.92,966 5486.66,966 5489.24,968.58 5499.97,968.58 5502.55,966 5513.29,966 5515.87,968.58 5526.61,968.58 5529.19,966 5539.93,966 5542.51,968.58 5553.24,968.58 5555.82,966 5569.88,966 5572.46,968.58 5583.2,968.58 5585.78,966 5599.84,966 5602.42,968.58 5613.16,968.58 5615.74,966 5629.8,966 5632.38,968.58 5643.12,968.58 5645.7,966 5659.76,966 5662.34,968.58 5673.07,968.58 5675.65,966 5686.39,966 5688.97,968.58 5699.71,968.58 5702.29,966 5739.66,966 5742.24,968.58 5752.98,968.58 5755.56,966 5769.62,966 5772.2,968.58 5782.94,968.58 5785.52,966 5799.58,966 5802.16,968.58 5812.9,968.58 5815.48,966 5829.54,966 5832.12,968.58 5842.85,968.58 5845.43,966 5866.16,966 5884.05,983.89 5884.05,1042.45 5872.13,1054.37 5849.8,1054.37 5838.83,1043.4 5838.83,1007.04 5827.19,995.39 5796,995.39 5783.09,1008.3 5783.09,1050.32 5775.9,1057.52 5747.71,1057.52 5741.41,1051.22 5741.41,1013.12 5729.29,1001 5718.56,1001 5715.98,998.42 5705.24,998.42 5702.66,1001 5690.86,1001 5687.93,1003.93 5680,1011.86 5680,1048.82 5673.82,1055 5646.11,1055 5638.93,1047.82 5638.93,1010.79 5629.14,1001 5563.75,1001 5550.87,1013.88 5550.87,1018 ; 5550.88,1018.01 5550.88,1032.86 5561.08,1043.06 5580.77,1043.06 5585.12,1047.4 5585.12,1058.11 5578.11,1065.12 5550.41,1065.12 5508.34,1065.12 5501.33,1058.11 5501.33,1047.4 5505.67,1043.06 5525.36,1043.06 5535.56,1032.86 5535.56,1018.01 5535.57,1013.88 5522.69,1001 5486.72,1001 5464,1023.72 5464,1095.51 5480.76,1112.27 5709.37,1112.27 5711.42,1114.32 v1(5711.42,1132.27)
  L7 SIGNAL w4: v1(4925.98,1232.28) 4925.98,1231.75 4942.48,1215.25 4942.48,1163.08 4952.76,1152.8 5026.69,1152.8
LVDSA6_P: J29.H26 U1.F13 | length 2841.1
  L7 SIGNAL w3.5: 5026.69,1122.8 5036.69,1132.8 5051.97,1132.8 5069.72,1115.04 5069.72,1067.13 5106.96,1029.89 5113.97,1022.88 5113.97,1003.82 5080.82,970.66 5080.82,943.32 5094.84,929.3 5122.18,929.3 5173.83,980.94 5192.88,980.94 5201.05,972.77 5201.05,953.72 5158.33,911 5158.33,883.66 5172.56,869.43 5172.94,869.05 5175.87,866.12 5179.99,862 5248.86,862 5266,879.14 5266,941.68 5280.32,956 5870.3,956 5894.05,979.75 5894.05,1046.59 5876.27,1064.37 5845.66,1064.37 5828.83,1047.54 5828.83,1011.18 5823.04,1005.39 5800.14,1005.39 5793.09,1012.44 5793.09,1054.47 5780.04,1067.52 5743.57,1067.52 5731.41,1055.36 5731.41,1017.26 5725.15,1011 5695,1011 5690,1016 5690,1052.96 5677.96,1065 5641.97,1065 5628.93,1051.96 5628.93,1014.93 5625,1011 5567.89,1011 5560.88,1018.01 5560.88,1028.72 5565.23,1033.06 5584.92,1033.06 5595.12,1043.26 5595.12,1058.11 ; 5491.32,1058.12 5491.32,1062.24 5504.2,1075.12 5546.27,1075.12 5582.25,1075.12 5595.13,1062.24 5595.13,1058.12 ; 5491.33,1058.11 5491.33,1043.26 5501.53,1033.06 5521.22,1033.06 5525.56,1028.72 5525.56,1018.01 5518.55,1011 5490.86,1011 5474,1027.86 5474,1091.37 5484.9,1102.27 5709.37,1102.27 5711.42,1100.22 v1(5711.42,1082.27)
  L7 SIGNAL w4: v1(4894.49,1232.28) 4909.49,1217.28 4909.49,1164.57 4921.27,1152.8 4932.2,1152.8 4941.73,1143.26 4941.73,1132.33 4951.27,1122.8 5026.69,1122.8
LVDSA7_N: J29.G25 U1.C13 | length 3082.5
  L7 SIGNAL w3.5: 5026.45,1216 5037.3,1205.15 5077.82,1205.15 5105.81,1177.16 5105.81,1151.87 5131.42,1126.25 5204.91,1126.25 5227.01,1104.15 5227.01,1017.22 5251.18,993.05 5272.56,993.05 5275.14,995.63 5285.88,995.63 5288.46,993.05 5299.2,993.05 5301.78,995.63 5312.52,995.63 5315.1,993.05 5329.16,993.05 5331.74,995.63 5342.47,995.63 5345.05,993.05 5359.11,993.05 5361.69,995.63 5372.43,995.63 5375.01,993.05 5389.07,993.05 5391.65,995.63 5402.39,995.63 5404.97,993.05 5413.37,993.05 5434.14,1013.82 5434.14,1124.5 5471.91,1162.27 5493.44,1162.27 5507.02,1148.69 5518.55,1148.69 5525.57,1155.71 5525.57,1218.23 5539.93,1232.59 5553.99,1232.59 5556.57,1235.17 5567.3,1235.17 5569.88,1232.59 5576.42,1232.59 5595.12,1213.89 5595.12,1154.03 5604,1145.14 5635.54,1145.14 5642.3,1151.9 5642.3,1202.22 5657.1,1217.02 5684.14,1217.02 5687.07,1214.09 5695,1206.16 5695,1171.27 5704,1162.27 5713.13,1162.27 5726.27,1175.41 5726.27,1196.46 5745.16,1215.35 5786.12,1215.35 5788.7,1217.93 5799.44,1217.93 5802.02,1215.35 5813.19,1215.35 5832.46,1234.63 5832.46,1258.35 5786.67,1304.14 5786.67,1415.35 5835.66,1464.34 5835.66,1605.3 5845.86,1615.5 5890.44,1615.5 5893.02,1618.08 5903.76,1618.08 5906.34,1615.5 5920.4,1615.5 5922.98,1618.08 5933.72,1618.08 5936.3,1615.5 ; v1(5761.42,1132.27) 5761.42,1150.22 5763.47,1152.27 5778.42,1152.27 5786.67,1144.02 5786.67,1090.7 5793.07,1084.3 5803.07,1074.3 5831.33,1074.3 5852.73,1095.7 5863.33,1106.3 5879.99,1106.3 5894.05,1120.36 5894.05,1148.69 5886.98,1155.76 5884.05,1158.69 5847.08,1158.69 5838.83,1166.94 5838.83,1179.55 5854.05,1194.76 5871.53,1194.76 5894.05,1217.28 5894.05,1254.6 5854.48,1294.17 5840.37,1308.28 5840.37,1386 5861.89,1407.52 5935.34,1407.52 5954,1426.18 5954,1447.7 5934.43,1467.27 5896.74,1467.27 5889.73,1474.28 5889.73,1484.98 5894.07,1489.33 5933.68,1489.33 5946.56,1502.2 5946.56,1506.33 5946.55,1521.18 5936.35,1531.38 5896.74,1531.38 5889.73,1538.39 5889.73,1549.1 5894.07,1553.44 5933.68,1553.44 5946.56,1566.32 5946.55,1586.31 ; 5936.35,1615.5 5946.55,1605.3 5946.55,1590.45 5946.56,1586.32
  L7 SIGNAL w4: v1(4988.98,1232.28) 5005.26,1216 5026.45,1216
LVDSA7_P: J29.G24 U1.D13 | length 3088.3
  L7 SIGNAL w3.5: 5025.21,1184.29 5036.07,1195.15 5073.68,1195.15 5095.81,1173.02 5095.81,1147.73 5124.35,1119.18 5127.28,1116.25 5200.76,1116.25 5217.01,1100.01 5217.01,1017.27 5217.09,1017.2 5217.09,1013.06 5222.87,1007.27 5222.92,1007.27 5247.07,983.12 5261.93,983.12 5262.01,983.05 5417.51,983.05 5444.14,1009.68 5444.14,1120.36 5476.05,1152.27 5489.3,1152.27 5502.88,1138.69 5522.69,1138.69 5535.57,1151.57 5535.57,1214.09 5544.07,1222.59 5572.28,1222.59 5580.77,1214.09 5585.12,1209.75 5585.12,1149.88 5599.86,1135.14 5639.68,1135.14 5652.3,1147.76 5652.3,1198.07 5661.24,1207.02 5680,1207.02 5685,1202.02 5685,1167.13 5699.86,1152.27 5717.27,1152.27 5736.27,1171.27 5736.27,1192.32 5749.3,1205.35 5769.51,1205.35 5817.33,1205.35 5842.46,1230.48 5842.46,1262.49 5839.53,1265.42 5836.6,1268.35 5796.67,1308.28 5796.67,1411.21 5845.66,1460.2 5845.66,1601.16 5850,1605.5 5932.21,1605.5 5936.55,1601.16 5936.55,1590.45 5936.55,1570.46 5929.54,1563.44 5889.93,1563.44 5879.73,1553.24 5879.73,1538.39 ; v1(5761.42,1182.27) 5761.42,1164.32 5763.47,1162.27 5783.09,1162.27 5796.67,1148.69 5796.67,1094.84 5800.14,1091.37 5807.21,1084.3 5827.19,1084.3 5842.73,1099.84 5859.19,1116.3 5875.84,1116.3 5884.05,1124.5 5884.05,1144.55 5879.9,1148.69 5842.94,1148.69 5828.83,1162.8 5828.83,1183.69 5849.9,1204.76 5867.38,1204.76 5884.05,1221.43 5884.05,1250.46 5866.16,1268.35 5850.34,1284.17 5830.37,1304.14 5830.37,1390.14 5852.3,1412.07 5854.81,1414.59 5857.74,1417.52 5931.19,1417.52 5944,1430.32 5944,1443.56 5930.29,1457.27 5892.6,1457.27 5879.72,1470.15 5879.72,1474.27 ; 5879.72,1538.38 5879.72,1534.26 5892.6,1521.38 5932.21,1521.38 5936.55,1517.04 5936.55,1506.34 5929.54,1499.33 5889.93,1499.33 5879.73,1489.13 5879.73,1474.28
  L7 SIGNAL w4: v1(4957.48,1232.28) 4972.48,1217.28 4972.48,1194.76 4982.95,1184.29 5025.21,1184.29
LVDSA8_N: J29.H37 U1.G14 | length 3082.8
  L12 SIGNAL w3.5: 4815.5,1100.58 4805.25,1090.33 4805.25,1026.65 4823.79,1008.11 4868.74,963.16 4868.74,914.74 4906.59,876.9 4946.92,836.56 5044.91,836.56 5050.77,830.71 5100.59,780.88 5106.45,775.03 5106.45,713.55 5109.03,710.97 5109.03,700.23 5106.45,697.65 5106.45,686.92 5109.03,684.34 5109.03,673.6 5106.45,671.02 5106.45,660.28 5109.03,657.7 5109.03,646.96 5106.45,644.38 5106.45,633.64 5109.03,631.06 5109.03,620.33 5106.45,617.75 5106.45,607.01 5109.03,604.43 5109.03,593.69 5106.45,591.11 5106.45,580.37 5109.03,577.79 5109.03,567.06 5106.45,564.48 5106.45,553.74 5109.03,551.16 5109.03,540.42 5106.45,537.84 5106.45,527.1 5109.03,524.52 5109.03,513.78 5106.45,511.2 5106.45,208.4 5180.95,133.9 5185.85,133.9 5197.37,133.9 5210.85,147.38 5230.18,166.71 5250.01,166.71 5269.35,147.38 5269.35,65 5282.82,51.52 5294.37,51.52 5307.85,65 5307.85,216.93 5327.18,236.26 5347.01,236.26 5366.35,216.93 5366.35,58.84 5379.82,45.37 5391.37,45.37 5404.85,58.84 5404.85,216.93 5424.18,236.26 5444.01,236.26 5463.35,216.93 5463.35,58.84 5476.82,45.37 5488.37,45.37 5501.85,58.84 5501.85,114.57 5521.18,133.9 5530,133.9 5553.9,133.9 5580,160 5580,474.14 5618.13,512.27 5709.37,512.27 5711.42,514.32 v1(5711.42,532.27)
  L12 SIGNAL w4: 4815.5,1100.58 4815.5,1174.5 4820.84,1179.85 4825.28,1184.29 4846.52,1184.29 v1(4862.99,1200.76)
LVDSA8_P: J29.H38 U1.H14 | length 3081.7
  L12 SIGNAL w3.5: 4785,1100.09 4795.25,1089.84 4795.25,1082.27 ; 4795.25,1082.16 4795.25,1022.51 4819.64,998.11 4835.47,982.29 4858.74,959.02 4858.74,910.6 4902.45,866.9 4942.78,826.56 5040.77,826.56 5096.45,770.88 5096.45,204.26 5176.81,123.9 5185.85,123.9 5201.51,123.9 5220.85,143.24 5234.32,156.71 5245.87,156.71 5259.35,143.24 5259.35,60.86 5278.68,41.52 5298.51,41.52 5317.85,60.86 5317.85,212.78 5331.32,226.26 5342.87,226.26 5356.35,212.78 5356.35,54.7 5375.68,35.37 5395.51,35.37 5414.85,54.7 5414.85,212.78 5428.32,226.26 5439.87,226.26 5453.35,212.78 5453.35,54.7 5472.68,35.37 5492.51,35.37 5511.85,54.7 5511.85,110.43 5525.32,123.9 5530,123.9 5558.04,123.9 5590,155.86 5590,470 5622.27,502.27 5709.37,502.27 5711.42,500.22 v1(5711.42,482.27)
  L12 SIGNAL w4: 4785,1100.09 4785,1175.5 4793.79,1184.29 4804.74,1184.29 4819.04,1198.59 4829.32,1198.59 v1(4831.5,1200.76)
LVDSA9_N: J29.H29 U1.E14 | length 2990.4
  L10 SIGNAL w3.5: 5031.75,1190.33 5037.68,1196.26 5067.37,1196.26 5092.07,1171.57 5092.07,1014.94 5125.63,981.38 5176.99,930.01 5176.99,733.77 5241.42,669.34 5244.35,666.41 5302.23,666.41 5322.12,686.3 5499.45,686.3 5521.27,708.13 5521.27,745.53 5501.93,764.86 5432.68,764.86 5430.1,767.44 5419.36,767.44 5416.78,764.86 5406.05,764.86 5403.47,767.44 5392.73,767.44 5390.15,764.86 5379.41,764.86 5376.83,767.44 5366.09,767.44 5363.51,764.86 5352.78,764.86 5350.2,767.44 5339.46,767.44 5336.88,764.86 5326.14,764.86 5323.56,767.44 5312.82,767.44 5310.24,764.86 5299.5,764.86 5296.92,767.44 5286.19,767.44 5283.61,764.86 5272.87,764.86 5270.29,767.44 5259.55,767.44 5256.97,764.86 5246.23,764.86 5243.65,767.44 5232.91,767.44 5230.34,764.86 5219.6,764.86 5206.12,778.33 5206.12,789.88 5219.6,803.36 5510.87,803.36 5527.73,820.22 5527.73,842.53 5508.4,861.86 5379.41,861.86 5376.83,864.44 5366.09,864.44 5363.51,861.86 5352.78,861.86 5350.2,864.44 5339.46,864.44 5336.88,861.86 5326.14,861.86 5323.56,864.44 5312.82,864.44 5310.24,861.86 5299.5,861.86 5296.92,864.44 5286.19,864.44 5283.61,861.86 5272.87,861.86 5270.29,864.44 5259.55,864.44 5256.97,861.86 5246.23,861.86 5243.65,864.44 5232.91,864.44 5230.34,861.86 5219.6,861.86 5206.12,875.33 5206.12,886.88 5219.6,900.36 5505.82,900.36 5521.27,915.81 5521.27,939.53 5501.93,958.86 5424.19,958.86 5410.72,972.33 5410.72,983.88 5424.19,997.36 5578.38,997.36 5611.42,964.32 5623.47,952.27 5709.37,952.27 5711.42,950.22 v1(5711.42,932.27)
  L10 SIGNAL w4: v1(4925.98,1200.76) 4940.98,1185.76 5026.69,1185.76 5031.25,1190.33 5031.75,1190.33
LVDSA9_P: J29.H28 U1.F14 | length 2992.4
  L10 SIGNAL w3.5: 5026.18,1216.76 5036.68,1206.26 5071.51,1206.26 5102.07,1175.71 5102.07,1019.08 5132.7,988.45 5186.99,934.16 5186.99,737.91 5248.49,676.41 5298.08,676.41 5317.98,696.3 5495.3,696.3 5511.27,712.27 5511.27,741.38 5497.79,754.86 5215.46,754.86 5196.12,774.19 5196.12,794.03 5215.46,813.36 5506.73,813.36 5517.73,824.36 5517.73,838.38 5504.26,851.86 5215.46,851.86 5196.12,871.19 5196.12,891.03 5215.46,910.36 5501.67,910.36 5511.27,919.95 5511.27,935.38 5497.79,948.86 5420.05,948.86 5417.12,951.79 5400.72,968.19 5400.72,988.03 5420.05,1007.36 5582.52,1007.36 5615.56,974.32 5627.61,962.27 5709.37,962.27 5711.42,964.32 v1(5711.42,982.27)
  L10 SIGNAL w4: v1(4894.49,1200.76) 4910.49,1216.76 5026.18,1216.76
